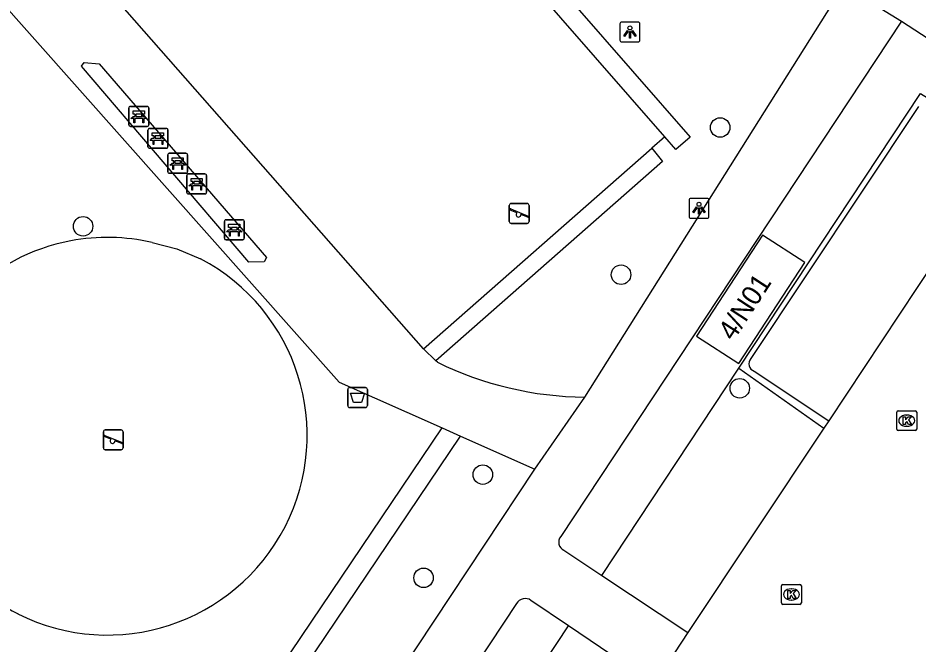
# Model space of a CAD drawing. Extents: x 159280 to 160375, y 384531 to 385872.
# Drawn here: x 159841.11 to 159886.24, y 384661.28 to 384692.69 of the extents above; entities that cross this region are included whole.
import ezdxf

# ---------------------------------------------------------------- set-up
doc = ezdxf.new("R2010")
doc.units = 0
for name, color, linetype in [('IMGEO_Afvalbak', 7, 'Continuous'), ('IMGEO_Bank', 7, 'Continuous'), ('IMGEO_Boom', 7, 'Continuous'), ('IMGEO_Groenvoorziening', 7, 'Continuous'), ('IMGEO_Haag', 7, 'Continuous'), ('IMGEO_Kolk', 7, 'Continuous'), ('IMGEO_Lichtpunt', 7, 'Continuous'), ('IMGEO_Pand', 7, 'Continuous'), ('IMGEO_Pand_nummerreeks', 7, 'Continuous'), ('IMGEO_Parkeervlak_open', 7, 'Continuous'), ('IMGEO_Rijbaan_lokaal_open', 7, 'Continuous'), ('IMGEO_Speelvoorziening', 7, 'Continuous'), ('IMGEO_Voetpad_halfverhard', 7, 'Continuous')]:
    doc.layers.add(name, color=color, linetype=linetype)

msp = doc.modelspace()

# ---------------------------------------------------------------- linework, layer by layer
at = {"layer": 'IMGEO_Afvalbak'}
for p, q in [((159857.641, 384673.249), (159857.641, 384674.049)), ((159857.641, 384674.049), (159857.641, 384673.249)), ((159857.741, 384674.149), (159858.531, 384674.149)), ((159858.531, 384674.149), (159857.741, 384674.149)), ((159858.631, 384674.049), (159858.631, 384673.249)), ((159858.631, 384673.249), (159858.631, 384674.049)), ((159858.531, 384673.149), (159857.741, 384673.149)), ((159857.741, 384673.149), (159858.531, 384673.149))]:
    msp.add_line(p, q, dxfattribs=at)
msp.add_lwpolyline([(159857.784, 384673.863), (159858.488, 384673.863), (159858.339, 384673.393), (159857.933, 384673.393), (159857.784, 384673.863)], dxfattribs=at)
for centre, start, end in [((159857.741, 384674.049), 90, 180), ((159857.741, 384674.049), 90, 180), ((159858.531, 384674.049), 0, 90), ((159858.531, 384674.049), 360, 90), ((159857.741, 384673.249), 180, 270), ((159857.741, 384673.249), 180, 270), ((159858.531, 384673.249), 270, 0), ((159858.531, 384673.249), 270, 0)]:
    msp.add_arc(centre, 0.1, start, end, dxfattribs=at)
at = {"layer": 'IMGEO_Bank'}
for p, q in [((159846.666, 384687.328), (159846.666, 384688.169)), ((159846.666, 384688.169), (159846.666, 384687.328)), ((159846.741, 384688.253), (159847.582, 384688.253)), ((159847.582, 384688.253), (159846.741, 384688.253)), ((159847.666, 384688.178), (159847.666, 384687.337)), ((159847.666, 384687.337), (159847.666, 384688.178)), ((159847.363, 384687.651), (159846.97, 384687.651)), ((159846.975, 384687.759), (159846.975, 384687.865)), ((159847.019, 384687.865), (159847.019, 384687.759)), ((159847.307, 384687.871), (159847.025, 384687.871)), ((159847.025, 384687.753), (159847.307, 384687.753)), ((159847.313, 384687.759), (159847.313, 384687.865)), ((159847.357, 384687.865), (159847.357, 384687.759)), ((159847.591, 384687.253), (159846.75, 384687.253)), ((159846.75, 384687.253), (159847.591, 384687.253)), ((159847.626, 384686.228), (159847.626, 384687.069)), ((159847.626, 384687.069), (159847.626, 384686.228)), ((159847.701, 384687.153), (159848.542, 384687.153)), ((159848.542, 384687.153), (159847.701, 384687.153)), ((159848.626, 384687.078), (159848.626, 384686.237)), ((159848.626, 384686.237), (159848.626, 384687.078)), ((159848.323, 384686.551), (159847.93, 384686.551)), ((159847.935, 384686.659), (159847.935, 384686.765)), ((159847.979, 384686.765), (159847.979, 384686.659)), ((159848.267, 384686.771), (159847.985, 384686.771)), ((159847.985, 384686.653), (159848.267, 384686.653)), ((159848.273, 384686.659), (159848.273, 384686.765)), ((159848.317, 384686.765), (159848.317, 384686.659)), ((159848.551, 384686.153), (159847.71, 384686.153)), ((159847.71, 384686.153), (159848.551, 384686.153)), ((159848.614, 384684.978), (159848.614, 384685.819)), ((159848.614, 384685.819), (159848.614, 384684.978)), ((159848.689, 384685.903), (159849.53, 384685.903)), ((159849.53, 384685.903), (159848.689, 384685.903)), ((159849.614, 384685.828), (159849.614, 384684.987)), ((159849.614, 384684.987), (159849.614, 384685.828)), ((159849.311, 384685.301), (159848.918, 384685.301)), ((159848.923, 384685.409), (159848.923, 384685.515)), ((159848.967, 384685.515), (159848.967, 384685.409)), ((159849.255, 384685.521), (159848.973, 384685.521)), ((159848.973, 384685.403), (159849.255, 384685.403)), ((159849.261, 384685.409), (159849.261, 384685.515)), ((159849.305, 384685.515), (159849.305, 384685.409)), ((159849.539, 384684.903), (159848.698, 384684.903)), ((159848.698, 384684.903), (159849.539, 384684.903)), ((159849.566, 384683.941), (159849.566, 384684.782)), ((159849.566, 384684.782), (159849.566, 384683.941)), ((159849.641, 384684.866), (159850.482, 384684.866)), ((159850.482, 384684.866), (159849.641, 384684.866)), ((159850.566, 384684.791), (159850.566, 384683.95)), ((159850.566, 384683.95), (159850.566, 384684.791)), ((159849.875, 384684.372), (159849.875, 384684.478)), ((159849.919, 384684.478), (159849.919, 384684.372)), ((159850.207, 384684.484), (159849.925, 384684.484)), ((159849.925, 384684.366), (159850.207, 384684.366)), ((159850.213, 384684.372), (159850.213, 384684.478)), ((159850.257, 384684.478), (159850.257, 384684.372)), ((159850.491, 384683.866), (159849.65, 384683.866)), ((159849.65, 384683.866), (159850.491, 384683.866)), ((159850.263, 384684.264), (159849.87, 384684.264)), ((159851.529, 384682.565), (159852.37, 384682.565)), ((159852.37, 384682.565), (159851.529, 384682.565)), ((159852.454, 384682.49), (159852.454, 384681.649)), ((159852.454, 384681.649), (159852.454, 384682.49)), ((159851.454, 384681.64), (159851.454, 384682.481)), ((159851.454, 384682.481), (159851.454, 384681.64)), ((159851.763, 384682.071), (159851.763, 384682.177)), ((159851.807, 384682.177), (159851.807, 384682.071)), ((159852.095, 384682.183), (159851.813, 384682.183)), ((159851.813, 384682.065), (159852.095, 384682.065)), ((159852.101, 384682.071), (159852.101, 384682.177)), ((159852.145, 384682.177), (159852.145, 384682.071)), ((159852.151, 384681.963), (159851.758, 384681.963)), ((159852.379, 384681.565), (159851.538, 384681.565)), ((159851.538, 384681.565), (159852.379, 384681.565))]:
    msp.add_line(p, q, dxfattribs=at)
for points in [[(159846.969, 384687.871), (159846.883, 384687.871), (159846.883, 384688.032), (159847.446, 384688.032), (159847.446, 384687.871), (159847.363, 384687.871)], [(159846.913, 384687.651), (159846.771, 384687.651), (159846.883, 384687.753), (159846.969, 384687.753)], [(159846.963, 384687.644), (159846.963, 384687.437), (159846.92, 384687.437), (159846.92, 384687.644)], [(159847.363, 384687.753), (159847.446, 384687.753), (159847.558, 384687.651), (159847.419, 384687.651)], [(159847.413, 384687.644), (159847.413, 384687.437), (159847.369, 384687.437), (159847.369, 384687.644)], [(159847.873, 384686.551), (159847.731, 384686.551), (159847.843, 384686.653), (159847.929, 384686.653)], [(159847.929, 384686.771), (159847.843, 384686.771), (159847.843, 384686.932), (159848.406, 384686.932), (159848.406, 384686.771), (159848.323, 384686.771)], [(159847.923, 384686.544), (159847.923, 384686.337), (159847.88, 384686.337), (159847.88, 384686.544)], [(159848.323, 384686.653), (159848.406, 384686.653), (159848.518, 384686.551), (159848.379, 384686.551)], [(159848.373, 384686.544), (159848.373, 384686.337), (159848.329, 384686.337), (159848.329, 384686.544)], [(159848.917, 384685.521), (159848.831, 384685.521), (159848.831, 384685.682), (159849.394, 384685.682), (159849.394, 384685.521), (159849.311, 384685.521)], [(159848.861, 384685.301), (159848.719, 384685.301), (159848.831, 384685.403), (159848.917, 384685.403)], [(159848.911, 384685.294), (159848.911, 384685.087), (159848.868, 384685.087), (159848.868, 384685.294)], [(159849.311, 384685.403), (159849.394, 384685.403), (159849.506, 384685.301), (159849.367, 384685.301)], [(159849.361, 384685.294), (159849.361, 384685.087), (159849.317, 384685.087), (159849.317, 384685.294)], [(159849.813, 384684.264), (159849.671, 384684.264), (159849.783, 384684.366), (159849.869, 384684.366)], [(159849.869, 384684.484), (159849.783, 384684.484), (159849.783, 384684.645), (159850.346, 384684.645), (159850.346, 384684.484), (159850.263, 384684.484)], [(159850.263, 384684.366), (159850.346, 384684.366), (159850.458, 384684.264), (159850.319, 384684.264)], [(159849.863, 384684.257), (159849.863, 384684.05), (159849.82, 384684.05), (159849.82, 384684.257)], [(159850.313, 384684.257), (159850.313, 384684.05), (159850.269, 384684.05), (159850.269, 384684.257)], [(159851.701, 384681.963), (159851.559, 384681.963), (159851.671, 384682.065), (159851.757, 384682.065)], [(159851.757, 384682.183), (159851.671, 384682.183), (159851.671, 384682.344), (159852.234, 384682.344), (159852.234, 384682.183), (159852.151, 384682.183)], [(159852.151, 384682.065), (159852.234, 384682.065), (159852.346, 384681.963), (159852.207, 384681.963)], [(159851.751, 384681.956), (159851.751, 384681.749), (159851.708, 384681.749), (159851.708, 384681.956)], [(159852.201, 384681.956), (159852.201, 384681.749), (159852.157, 384681.749), (159852.157, 384681.956)]]:
    msp.add_lwpolyline(points, dxfattribs=at)
for centre, radius, start, end in [((159846.744, 384688.175), 0.0779, 92.4484, 184.2845), ((159846.744, 384688.175), 0.0779, 92.4484, 184.2845), ((159847.588, 384688.175), 0.0779, 2.4484, 94.2845), ((159847.588, 384688.175), 0.0779, 2.4484, 94.2845), ((159846.913, 384687.644), 0.00671, 2.8957, 87.1043), ((159846.97, 384687.644), 0.00671, 92.8957, 177.1043), ((159846.968, 384687.864), 0.00671, 2.8957, 87.1043), ((159846.968, 384687.76), 0.00671, 272.8957, 357.1043), ((159847.025, 384687.864), 0.00671, 92.8957, 177.1043), ((159847.025, 384687.76), 0.00671, 182.8957, 267.1043), ((159847.307, 384687.864), 0.00671, 2.8957, 87.1043), ((159847.307, 384687.76), 0.00671, 272.8957, 357.1043), ((159847.364, 384687.864), 0.00671, 92.8957, 177.1043), ((159847.364, 384687.76), 0.00671, 182.8957, 267.1043), ((159847.362, 384687.644), 0.00671, 2.8957, 87.1043), ((159847.419, 384687.644), 0.00671, 92.8957, 177.1043), ((159846.744, 384687.331), 0.0779, 182.4484, 274.2845), ((159846.744, 384687.331), 0.0779, 182.4484, 274.2845), ((159847.588, 384687.331), 0.0779, 272.4484, 4.2845), ((159847.588, 384687.331), 0.0779, 272.4484, 4.2845), ((159847.704, 384687.075), 0.0779, 92.4484, 184.2845), ((159847.704, 384687.075), 0.0779, 92.4484, 184.2845), ((159848.548, 384687.075), 0.0779, 2.4484, 94.2845), ((159848.548, 384687.075), 0.0779, 2.4484, 94.2845), ((159847.873, 384686.544), 0.00671, 2.8957, 87.1043), ((159847.93, 384686.544), 0.00671, 92.8957, 177.1043), ((159847.928, 384686.764), 0.00671, 2.8957, 87.1043), ((159847.928, 384686.66), 0.00671, 272.8957, 357.1043), ((159847.985, 384686.764), 0.00671, 92.8957, 177.1043), ((159847.985, 384686.66), 0.00671, 182.8957, 267.1043), ((159848.267, 384686.764), 0.00671, 2.8957, 87.1043), ((159848.267, 384686.66), 0.00671, 272.8957, 357.1043), ((159848.324, 384686.764), 0.00671, 92.8957, 177.1043), ((159848.324, 384686.66), 0.00671, 182.8957, 267.1043), ((159848.322, 384686.544), 0.00671, 2.8957, 87.1043), ((159848.379, 384686.544), 0.00671, 92.8957, 177.1043), ((159847.704, 384686.231), 0.0779, 182.4484, 274.2845), ((159847.704, 384686.231), 0.0779, 182.4484, 274.2845), ((159848.548, 384686.231), 0.0779, 272.4484, 4.2845), ((159848.548, 384686.231), 0.0779, 272.4484, 4.2845), ((159848.692, 384685.825), 0.0779, 92.4484, 184.2845), ((159848.692, 384685.825), 0.0779, 92.4484, 184.2845), ((159849.536, 384685.825), 0.0779, 2.4484, 94.2845), ((159849.536, 384685.825), 0.0779, 2.4484, 94.2845), ((159848.861, 384685.294), 0.00671, 2.8957, 87.1043), ((159848.918, 384685.294), 0.00671, 92.8957, 177.1043), ((159848.916, 384685.514), 0.00671, 2.8957, 87.1043), ((159848.916, 384685.41), 0.00671, 272.8957, 357.1043), ((159848.973, 384685.514), 0.00671, 92.8957, 177.1043), ((159848.973, 384685.41), 0.00671, 182.8957, 267.1043), ((159849.255, 384685.514), 0.00671, 2.8957, 87.1043), ((159849.255, 384685.41), 0.00671, 272.8957, 357.1043), ((159849.312, 384685.514), 0.00671, 92.8957, 177.1043), ((159849.312, 384685.41), 0.00671, 182.8957, 267.1043), ((159849.31, 384685.294), 0.00671, 2.8957, 87.1043), ((159849.367, 384685.294), 0.00671, 92.8957, 177.1043), ((159848.692, 384684.981), 0.0779, 182.4484, 274.2845), ((159848.692, 384684.981), 0.0779, 182.4484, 274.2845), ((159849.536, 384684.981), 0.0779, 272.4484, 4.2845), ((159849.536, 384684.981), 0.0779, 272.4484, 4.2845), ((159849.644, 384684.788), 0.0779, 92.4484, 184.2845), ((159849.644, 384684.788), 0.0779, 92.4484, 184.2845), ((159850.488, 384684.788), 0.0779, 2.4484, 94.2845), ((159850.488, 384684.788), 0.0779, 2.4484, 94.2845), ((159849.868, 384684.477), 0.00671, 2.8957, 87.1043), ((159849.868, 384684.373), 0.00671, 272.8957, 357.1043), ((159849.925, 384684.477), 0.00671, 92.8957, 177.1043), ((159849.925, 384684.373), 0.00671, 182.8957, 267.1043), ((159850.207, 384684.477), 0.00671, 2.8957, 87.1043), ((159850.207, 384684.373), 0.00671, 272.8957, 357.1043), ((159850.264, 384684.477), 0.00671, 92.8957, 177.1043), ((159850.264, 384684.373), 0.00671, 182.8957, 267.1043), ((159849.644, 384683.944), 0.0779, 182.4484, 274.2845), ((159849.644, 384683.944), 0.0779, 182.4484, 274.2845), ((159849.813, 384684.257), 0.00671, 2.8957, 87.1043), ((159849.87, 384684.257), 0.00671, 92.8957, 177.1043), ((159850.262, 384684.257), 0.00671, 2.8957, 87.1043), ((159850.319, 384684.257), 0.00671, 92.8957, 177.1043), ((159850.488, 384683.944), 0.0779, 272.4484, 4.2845), ((159850.488, 384683.944), 0.0779, 272.4484, 4.2845), ((159851.532, 384682.487), 0.0779, 92.4484, 184.2845), ((159851.532, 384682.487), 0.0779, 92.4484, 184.2845), ((159852.376, 384682.487), 0.0779, 2.4484, 94.2845), ((159852.376, 384682.487), 0.0779, 2.4484, 94.2845), ((159851.756, 384682.176), 0.00671, 2.8957, 87.1043), ((159851.756, 384682.072), 0.00671, 272.8957, 357.1043), ((159851.813, 384682.176), 0.00671, 92.8957, 177.1043), ((159851.813, 384682.072), 0.00671, 182.8957, 267.1043), ((159852.095, 384682.176), 0.00671, 2.8957, 87.1043), ((159852.095, 384682.072), 0.00671, 272.8957, 357.1043), ((159852.152, 384682.176), 0.00671, 92.8957, 177.1043), ((159852.152, 384682.072), 0.00671, 182.8957, 267.1043), ((159851.532, 384681.643), 0.0779, 182.4484, 274.2845), ((159851.532, 384681.643), 0.0779, 182.4484, 274.2845), ((159851.701, 384681.956), 0.00671, 2.8957, 87.1043), ((159851.758, 384681.956), 0.00671, 92.8957, 177.1043), ((159852.15, 384681.956), 0.00671, 2.8957, 87.1043), ((159852.207, 384681.956), 0.00671, 92.8957, 177.1043), ((159852.376, 384681.643), 0.0779, 272.4484, 4.2845), ((159852.376, 384681.643), 0.0779, 272.4484, 4.2845)]:
    msp.add_arc(centre, radius, start, end, dxfattribs=at)
at = {"layer": 'IMGEO_Boom'}
for centre in [(159876.314, 384687.195), (159844.372, 384682.239), (159871.347, 384679.812), (159877.298, 384674.114), (159864.415, 384669.782), (159861.443, 384664.605)]:
    msp.add_circle(centre, 0.489, dxfattribs=at)
at = {"layer": 'IMGEO_Groenvoorziening'}
for points in [[(159873.538, 384686.724), (159872.889, 384686.155)], [(159847.831, 384681.428), (159849.079, 384681.109), (159850.263, 384680.604)], [(159870.387, 384664.721), (159877.255, 384675.123)], [(159842.792, 384643.041), (159853.801, 384659.395), (159862.37, 384672.124)], [(159842.545, 384640.883), (159863.298, 384671.711)], [(159856.983, 384644.42), (159868.715, 384662.189)]]:
    msp.add_lwpolyline(points, dxfattribs=at)
for centre, radius, start, end in [((159845.599, 384671.707), 9.974, 77.0691, 100.6849), ((159845.591, 384671.718), 9.962, 100.6469, 135.387), ((159845.594, 384671.747), 10.013, 243.383, 62.2047), ((159845.597, 384671.703), 9.975, 184.3548, 243.2586)]:
    msp.add_arc(centre, radius, start, end, dxfattribs=at)
at = {"layer": 'IMGEO_Haag'}
for points in [[(159854.423, 384708.639), (159853.849, 384709.311), (159854.572, 384709.914), (159874.803, 384686.719), (159874.093, 384686.089), (159873.538, 384686.724)], [(159873.538, 384686.724), (159854.423, 384708.639)], [(159877.255, 384675.123), (159886.356, 384688.908), (159890.803, 384686.136)], [(159861.434, 384676.096), (159872.889, 384686.155)], [(159872.889, 384686.155), (159873.416, 384685.492), (159862.06, 384675.496)], [(159877.255, 384675.123), (159881.517, 384672.113)]]:
    msp.add_lwpolyline(points, dxfattribs=at)
at = {"layer": 'IMGEO_Kolk'}
for p, q in [((159885.168, 384672.062), (159885.168, 384672.914)), ((159885.243, 384672.988), (159886.095, 384672.988)), ((159885.656, 384672.768), (159885.681, 384672.768)), ((159886.169, 384672.914), (159886.169, 384672.062)), ((159885.679, 384672.208), (159885.654, 384672.208)), ((159886.095, 384671.988), (159885.243, 384671.988)), ((159879.387, 384663.343), (159879.387, 384664.195)), ((159879.462, 384664.269), (159880.314, 384664.269)), ((159879.875, 384664.049), (159879.9, 384664.049)), ((159880.388, 384664.195), (159880.388, 384663.343)), ((159880.314, 384663.269), (159879.462, 384663.269)), ((159879.898, 384663.489), (159879.873, 384663.489))]:
    msp.add_line(p, q, dxfattribs=at)
for points in [[(159885.168, 384672.062), (159885.168, 384672.914)], [(159885.243, 384672.988), (159886.095, 384672.988)], [(159885.489, 384672.688), (159885.612, 384672.688), (159885.612, 384672.537), (159885.742, 384672.688), (159885.906, 384672.688), (159885.76, 384672.537), (159885.913, 384672.288), (159885.761, 384672.288), (159885.676, 384672.452), (159885.612, 384672.385), (159885.612, 384672.288), (159885.489, 384672.288), (159885.489, 384672.688)], [(159886.169, 384672.914), (159886.169, 384672.062)], [(159886.095, 384671.988), (159885.243, 384671.988)], [(159879.387, 384663.343), (159879.387, 384664.195)], [(159879.462, 384664.269), (159880.314, 384664.269)], [(159880.388, 384664.195), (159880.388, 384663.343)], [(159879.708, 384663.969), (159879.831, 384663.969), (159879.831, 384663.818), (159879.961, 384663.969), (159880.125, 384663.969), (159879.979, 384663.818), (159880.132, 384663.569), (159879.98, 384663.569), (159879.895, 384663.733), (159879.831, 384663.666), (159879.831, 384663.569), (159879.708, 384663.569), (159879.708, 384663.969)], [(159880.314, 384663.269), (159879.462, 384663.269)]]:
    msp.add_lwpolyline(points, dxfattribs=at)
for centre, start, end in [((159885.245, 384672.912), 91.552, 178.448), ((159885.245, 384672.912), 91.552, 178.448), ((159886.093, 384672.912), 1.552, 88.448), ((159886.093, 384672.912), 1.552, 88.448), ((159885.245, 384672.064), 181.552, 268.448), ((159885.245, 384672.064), 181.552, 268.448), ((159886.093, 384672.064), 271.552, 358.448), ((159886.093, 384672.064), 271.552, 358.448), ((159879.464, 384664.193), 91.552, 178.448), ((159879.464, 384664.193), 91.552, 178.448), ((159880.312, 384664.193), 1.552, 88.448), ((159880.312, 384664.193), 1.552, 88.448), ((159879.464, 384663.345), 181.552, 268.448), ((159879.464, 384663.345), 181.552, 268.448), ((159880.312, 384663.345), 271.552, 358.448), ((159880.312, 384663.345), 271.552, 358.448)]:
    msp.add_arc(centre, 0.0765, start, end, dxfattribs=at)
for centre, major_axis, ratio, start_param, end_param in [((159885.655, 384672.488), (-0.387, 0.002), 0.722429, 4.712389, 7.853982), ((159885.68, 384672.488), (-0.39, 0.002), 0.717154, 1.570796, 4.712389), ((159879.874, 384663.769), (-0.387, 0.002), 0.722429, 4.712389, 7.853982), ((159879.899, 384663.769), (-0.39, 0.002), 0.717154, 1.570796, 4.712389)]:
    msp.add_ellipse(centre, major_axis=major_axis, ratio=ratio, start_param=start_param, end_param=end_param, dxfattribs=at)
at = {"layer": 'IMGEO_Lichtpunt'}
for p, q in [((159872.193, 384692.487), (159871.385, 384692.487)), ((159872.193, 384692.487), (159871.385, 384692.487)), ((159871.291, 384692.392), (159871.291, 384691.585)), ((159871.291, 384692.392), (159871.291, 384691.585)), ((159872.287, 384691.585), (159872.287, 384692.392)), ((159872.287, 384691.585), (159872.287, 384692.392)), ((159871.385, 384691.491), (159872.193, 384691.491)), ((159871.385, 384691.491), (159872.193, 384691.491)), ((159874.755, 384683.546), (159874.755, 384682.739)), ((159874.755, 384683.546), (159874.755, 384682.739)), ((159875.657, 384683.641), (159874.849, 384683.641)), ((159875.657, 384683.641), (159874.849, 384683.641)), ((159875.751, 384682.739), (159875.751, 384683.546)), ((159875.751, 384682.739), (159875.751, 384683.546)), ((159874.849, 384682.645), (159875.657, 384682.645)), ((159874.849, 384682.645), (159875.657, 384682.645))]:
    msp.add_line(p, q, dxfattribs=at)
for points in [[(159871.665, 384692.056), (159871.704, 384692.028), (159871.516, 384691.766), (159871.478, 384691.793), (159871.665, 384692.056)], [(159871.767, 384692.008), (159871.814, 384692.008), (159871.814, 384691.686), (159871.767, 384691.686), (159871.767, 384692.008)], [(159871.877, 384692.028), (159871.915, 384692.055), (159872.102, 384691.793), (159872.063, 384691.765), (159871.877, 384692.028)], [(159875.129, 384683.21), (159875.168, 384683.182), (159874.98, 384682.92), (159874.942, 384682.947), (159875.129, 384683.21)], [(159875.231, 384683.162), (159875.278, 384683.162), (159875.278, 384682.84), (159875.231, 384682.84), (159875.231, 384683.162)], [(159875.341, 384683.182), (159875.379, 384683.209), (159875.566, 384682.947), (159875.527, 384682.919), (159875.341, 384683.182)]]:
    msp.add_lwpolyline(points, dxfattribs=at)
for centre in [(159871.79, 384692.19), (159875.254, 384683.344)]:
    msp.add_circle(centre, 0.0994, dxfattribs=at)
for centre, start, end in [((159871.385, 384692.392), 90, 180), ((159871.385, 384692.392), 90, 180), ((159872.193, 384692.392), 0, 90), ((159872.193, 384692.392), 0, 90), ((159871.385, 384691.585), 180, 270), ((159871.385, 384691.585), 180, 270), ((159872.193, 384691.585), 270, 0), ((159872.193, 384691.585), 270, 360), ((159874.849, 384683.546), 90, 180), ((159874.849, 384683.546), 90, 180), ((159875.657, 384683.546), 0, 90), ((159875.657, 384683.546), 0, 90), ((159874.849, 384682.739), 180, 270), ((159874.849, 384682.739), 180, 270), ((159875.657, 384682.739), 270, 0), ((159875.657, 384682.739), 270, 360)]:
    msp.add_arc(centre, 0.0946, start, end, dxfattribs=at)
at = {"layer": 'IMGEO_Pand'}
msp.add_lwpolyline([(159880.562, 384680.419), (159878.44, 384681.802), (159875.137, 384676.734), (159877.259, 384675.351), (159880.562, 384680.419)], dxfattribs=at)
at = {"layer": 'IMGEO_Parkeervlak_open'}
for points in [[(159886.255, 384688.244), (159877.859, 384675.606)], [(159878.021, 384674.972), (159881.764, 384672.483)]]:
    msp.add_lwpolyline(points, dxfattribs=at)
msp.add_arc((159878.151, 384675.343), 0.393, 137.9557, 250.7114, dxfattribs=at)
at = {"layer": 'IMGEO_Rijbaan_lokaal_open'}
for points in [[(159890.622, 384685.865), (159881.764, 384672.483)], [(159881.517, 384672.113), (159874.692, 384661.854)], [(159881.764, 384672.483), (159881.517, 384672.113)], [(159874.692, 384661.854), (159873.001, 384659.279)]]:
    msp.add_lwpolyline(points, dxfattribs=at)
at = {"layer": 'IMGEO_Speelvoorziening'}
for p, q in [((159865.744, 384682.484), (159865.744, 384683.284)), ((159865.744, 384683.284), (159865.744, 384682.484)), ((159866.127, 384682.912), (159865.788, 384683.049)), ((159865.813, 384683.109), (159866.689, 384682.756)), ((159865.844, 384683.384), (159866.634, 384683.384)), ((159866.634, 384683.384), (159865.844, 384683.384)), ((159866.734, 384683.284), (159866.734, 384682.484)), ((159866.734, 384682.484), (159866.734, 384683.284)), ((159866.665, 384682.696), (159866.325, 384682.833)), ((159866.634, 384682.384), (159865.844, 384682.384)), ((159865.844, 384682.384), (159866.634, 384682.384)), ((159845.387, 384671.127), (159845.387, 384671.927)), ((159845.387, 384671.927), (159845.387, 384671.127)), ((159845.77, 384671.555), (159845.431, 384671.692)), ((159845.456, 384671.752), (159846.332, 384671.399)), ((159845.487, 384672.027), (159846.277, 384672.027)), ((159846.277, 384672.027), (159845.487, 384672.027)), ((159846.377, 384671.927), (159846.377, 384671.127)), ((159846.377, 384671.127), (159846.377, 384671.927)), ((159846.308, 384671.339), (159845.968, 384671.476)), ((159846.277, 384671.027), (159845.487, 384671.027)), ((159845.487, 384671.027), (159846.277, 384671.027))]:
    msp.add_line(p, q, dxfattribs=at)
for centre, radius, start, end in [((159865.844, 384683.284), 0.1, 90, 180), ((159865.844, 384683.284), 0.1, 90, 180), ((159865.801, 384683.079), 0.0327, 68.078, 248.078), ((159866.634, 384683.284), 0.1, 0, 90), ((159866.634, 384683.284), 0.1, 360, 90), ((159865.844, 384682.484), 0.1, 180, 270), ((159865.844, 384682.484), 0.1, 180, 270), ((159866.206, 384682.822), 0.12, 130.9928, 5.1632), ((159866.634, 384682.484), 0.1, 270, 0), ((159866.634, 384682.484), 0.1, 270, 0), ((159866.677, 384682.726), 0.0327, 248.078, 68.078), ((159845.487, 384671.927), 0.1, 90, 180), ((159845.487, 384671.927), 0.1, 90, 180), ((159845.444, 384671.722), 0.0327, 68.078, 248.078), ((159846.277, 384671.927), 0.1, 0, 90), ((159846.277, 384671.927), 0.1, 360, 90), ((159845.849, 384671.465), 0.12, 130.9928, 5.1632), ((159846.32, 384671.369), 0.0327, 248.078, 68.078), ((159845.487, 384671.127), 0.1, 180, 270), ((159845.487, 384671.127), 0.1, 180, 270), ((159846.277, 384671.127), 0.1, 270, 0), ((159846.277, 384671.127), 0.1, 270, 0)]:
    msp.add_arc(centre, radius, start, end, dxfattribs=at)
at = {"layer": 'IMGEO_Voetpad_halfverhard'}
for points in [[(159800.8, 384713.041), (159815.747, 384695.717), (159816.731, 384696.515), (159825.142, 384686.909), (159835.436, 384698.96), (159857.22, 384674.413), (159862.37, 384672.124)], [(159861.434, 384676.096), (159842.315, 384697.861)], [(159869.522, 384673.668), (159882.522, 384694.32)], [(159882.522, 384694.32), (159885.403, 384692.531)], [(159885.403, 384692.531), (159868.322, 384666.681)], [(159885.403, 384692.531), (159892.14, 384688.148)], [(159844.293, 384690.268), (159844.419, 384690.452), (159845.183, 384690.388), (159853.567, 384680.671), (159853.449, 384680.459), (159852.69, 384680.436), (159844.293, 384690.268)], [(159862.06, 384675.496), (159861.434, 384676.096)], [(159862.142, 384675.417), (159862.06, 384675.496)], [(159867.03, 384670.053), (159869.522, 384673.668)], [(159862.37, 384672.124), (159863.298, 384671.711)], [(159863.298, 384671.711), (159867.03, 384670.053)], [(159846.96, 384635.618), (159846.839, 384639.549), (159867.03, 384670.053)], [(159868.485, 384665.988), (159870.387, 384664.721)], [(159870.387, 384664.721), (159874.692, 384661.854)], [(159866.11, 384663.309), (159854.757, 384646.133)], [(159868.715, 384662.189), (159866.825, 384663.472)], [(159873.001, 384659.279), (159868.715, 384662.189)]]:
    msp.add_lwpolyline(points, dxfattribs=at)
for centre, radius, start, end in [((159946.59, 384787.793), 110.32, 233.94935, 241.49163), ((159869.705, 384690.886), 17.219, 243.9445, 269.3901), ((159868.663, 384666.396), 0.445, 140.0579, 246.414), ((159866.537, 384663.084), 0.483, 53.4244, 152.2604)]:
    msp.add_arc(centre, radius, start, end, dxfattribs=at)

# ---------------------------------------------------------------- texts
at = {"layer": 'IMGEO_Pand_nummerreeks'}
msp.add_text('4/N01', height=1, rotation=56.9062, dxfattribs=at).set_placement((159876.979, 384676.446))

doc.saveas('drawing.dxf')
